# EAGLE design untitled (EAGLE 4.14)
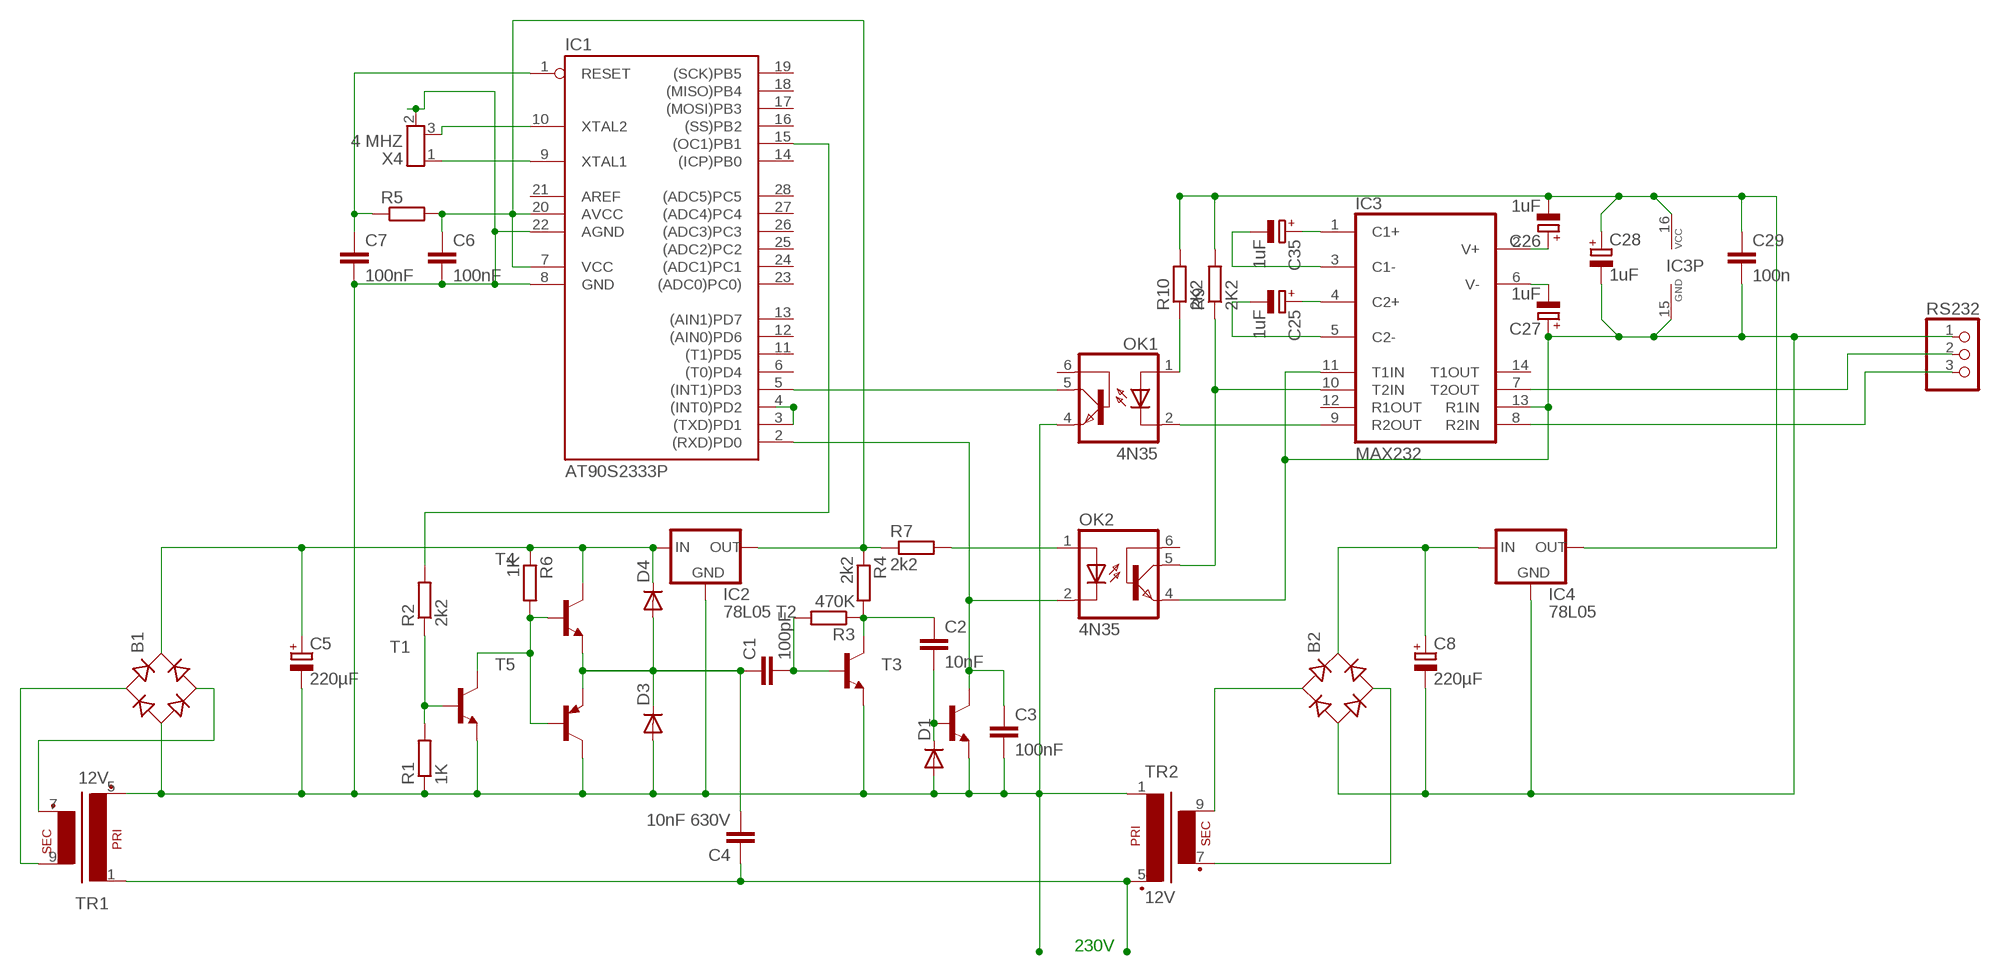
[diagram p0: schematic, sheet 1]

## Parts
B1  B-DIL  [B-DIL]
B2  B-DIL  [B-DIL]
C1  100pF  C-EU050-024X044  [C050-024X044]
C2  10nF  C-EU025-024X044  [C025-024X044]
C3  100nF  C-EU050-024X044  [C050-024X044]
C4  10nF 630V  C-EU102-043X133  [C102-043X133]
C5  220µF  CPOL-EUE5-10.5  [E5-10,5]
C6  100nF  C-EU050-024X044  [C050-024X044]
C7  100nF  C-EU050-024X044  [C050-024X044]
C8  220µF  CPOL-EUE5-10.5  [E5-10,5]
C25  1uF  CPOL-EUE2.5-5  [E2,5-5]
C26  1uF  CPOL-EUE2.5-5  [E2,5-5]
C27  1uF  CPOL-EUE2.5-5  [E2,5-5]
C28  1uF  CPOL-EUE2.5-5  [E2,5-5]
C29  100n  C-EUC1206  [C1206]
C35  1uF  CPOL-EUE2.5-5  [E2,5-5]
D1  DIODE-D-2.5  [D-2.5]
D3  DIODE-D-5  [D-5]
D4  DIODE-D-2.5  [D-2.5]
IC1  AT90S2333P  [DIL28-3]
IC2  78L05  78XXS  [78XXS]
IC3  MAX232  [DIL16]
IC4  78L05  78XXS  [78XXS]
OK1  4N35  [DIL06]
OK2  4N35  [DIL06]
R1  1K  R-EU_0207/5V  [0207/5V]
R2  2k2  R-EU_0207/5V  [0207/5V]
R3  470K  R-EU_0207/2V  [0207/2V]
R4  2k2  R-EU_0207/2V  [0207/2V]
R5  R-EU_0207/2V  [0207/2V]
R6  1K  R-EU_0207/2V  [0207/2V]
R7  2k2  R-EU_0207/2V  [0207/2V]
R9  2K2  R-EU_0207/2V  [0207/2V]
R10  2K2  R-EU_0207/2V  [0207/2V]
RS232  PINHD-1X3  [1X03]
T1  BC547A-NPN-TO92-EBC  [TO92-EBC]
T2  BC547A-NPN-TO92-EBC  [TO92-EBC]
T3  BC547A-NPN-TO92-EBC  [TO92-EBC]
T4  BC547A-NPN-TO92-EBC  [TO92-EBC]
T5  BC558A-PNP-TO92-EBC  [TO92-EBC]
TR1  12V  EI30-1  [EI30-1]
TR2  12V  EI30-1  [EI30-1]
X4  4 MHZ  RESONZTT  [RESONZTT]

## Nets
GND1: B1.- C3.2 C5.- C6.2 C7.2 D1.A D3.A IC1.8(GND) IC1.22(AGND) IC2.GND OK1.4(EMI) R1.1 T1.E T2.E T3.E T5.C TR1.5 TR2.1 X4.2(GND)
GND2: B2.- C8.- C27.+ C28.- C29.2 IC3.11(T1IN) IC3.13(R1IN) IC3.15(GND) IC4.GND OK2.4(EMI) RS232.1
N$1: R1.2 R2.1 T1.B
N$2: OK1.1(A) R10.1
N$3: C2.1 R3.1 R4.2 T2.C
N$4: C2.2 D1.C T3.B
N$5: IC1.15((OC1)PB1) R2.2
N$6: C1.2 R3.2 T2.B
N$7: IC1.3((TXD)PD1) IC1.4((INT0)PD2)
N$8: C4.1 TR1.1 TR2.5
N$9: OK2.1(A) R7.2
N$10: IC3.10(T2IN) OK2.5(COL) R9.1
N$11: C7.1 IC1.1(RESET) R5.1
N$12: C6.1 IC1.7(VCC) IC1.20(AVCC) IC2.OUT R4.1 R5.2 R7.1
N$13: C1.1 C4.2 D3.C D4.A T4.E T5.E
N$14: B1.+ C5.+ D4.C IC2.IN R6.1 T4.C
N$15: R6.2 T1.C T4.B T5.B
N$16: IC1.5((INT1)PD3) OK1.5(COL)
N$17: C3.1 IC1.2((RXD)PD0) OK2.2(C) T3.C
N$18: B2.AC1 TR2.9
N$19: B1.AC2 TR1.7
N$20: B1.AC1 TR1.9
N$21: B2.AC2 TR2.7
N$23: B2.+ C8.+ IC4.IN
N$52: IC1.9(XTAL1) X4.1(X1)
N$53: IC1.10(XTAL2) X4.3(X2)
N$64: C25.+ IC3.4(C2+)
N$66: C35.+ IC3.1(C1+)
N$67: C25.- IC3.5(C2-)
N$68: C35.- IC3.3(C1-)
N$69: C27.- IC3.6(V-)
N$70: C26.+ IC3.2(V+)
N$73: IC3.8(R2IN) RS232.3
N$74: IC3.9(R2OUT) OK1.2(C)
N$77: IC3.7(T2OUT) RS232.2
VCCBATT: C26.- C28.+ C29.1 IC3.16(VCC) IC4.OUT R9.2 R10.2
Unconnected: IC1.6((T0)PD4) IC1.11((T1)PD5) IC1.12((AIN0)PD6) IC1.13((AIN1)PD7) IC1.14((ICP)PB0) IC1.16((SS)PB2) IC1.17((MOSI)PB3) IC1.18((MISO)PB4) IC1.19((SCK)PB5) IC1.23((ADC0)PC0)) IC1.24((ADC1)PC1) IC1.25((ADC2)PC2) IC1.26((ADC3)PC3) IC1.27((ADC4)PC4) IC1.28((ADC5)PC5) IC3.12(R1OUT) IC3.14(T1OUT) OK1.6(BAS) OK2.6(BAS)

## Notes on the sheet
- 230V

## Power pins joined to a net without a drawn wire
AREF: IC1.21(AREF)

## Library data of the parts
B1 B2 = rectifier:B-DIL: RECTIFIER
C1-C4 C6 C7 C29 = rcl:C-EU: CAPACITOR, European symbol
C5 C8 C25-C28 C35 = rcl:CPOL-EU: POLARIZED CAPACITOR, European symbol
D1 D3 D4 = diode:DIODE-: DIODE
IC1 = atmel:AT90S2333P: MICROCONTROLLER 2 Kbytes FLASH 128 bytes SRAM 128 bytes EEPROM UART 6-channel 10-bit ADC
IC2 IC4 = v-reg:78XXS: VOLTAGE REGULATOR
IC3 = maxim:MAX232: RS232 TRANSEIVER
OK1 OK2 = optocoupler:4N35: MOTOROLA OPTO COUPLER
R1-R7 R9 R10 = rcl:R-EU_: RESISTOR, European symbol
RS232 = pinhead:PINHD-1X3: PIN HEADER
T1-T4 = transistor:*-NPN-: NPN Transistror
T5 = transistor:*-PNP-: PNP Transistror
TR1 TR2 = trafo:EI30-1: TRANSFORMER 1 primary winding, 1 secondary winding ERA
X4 = ADS:RESONZTT

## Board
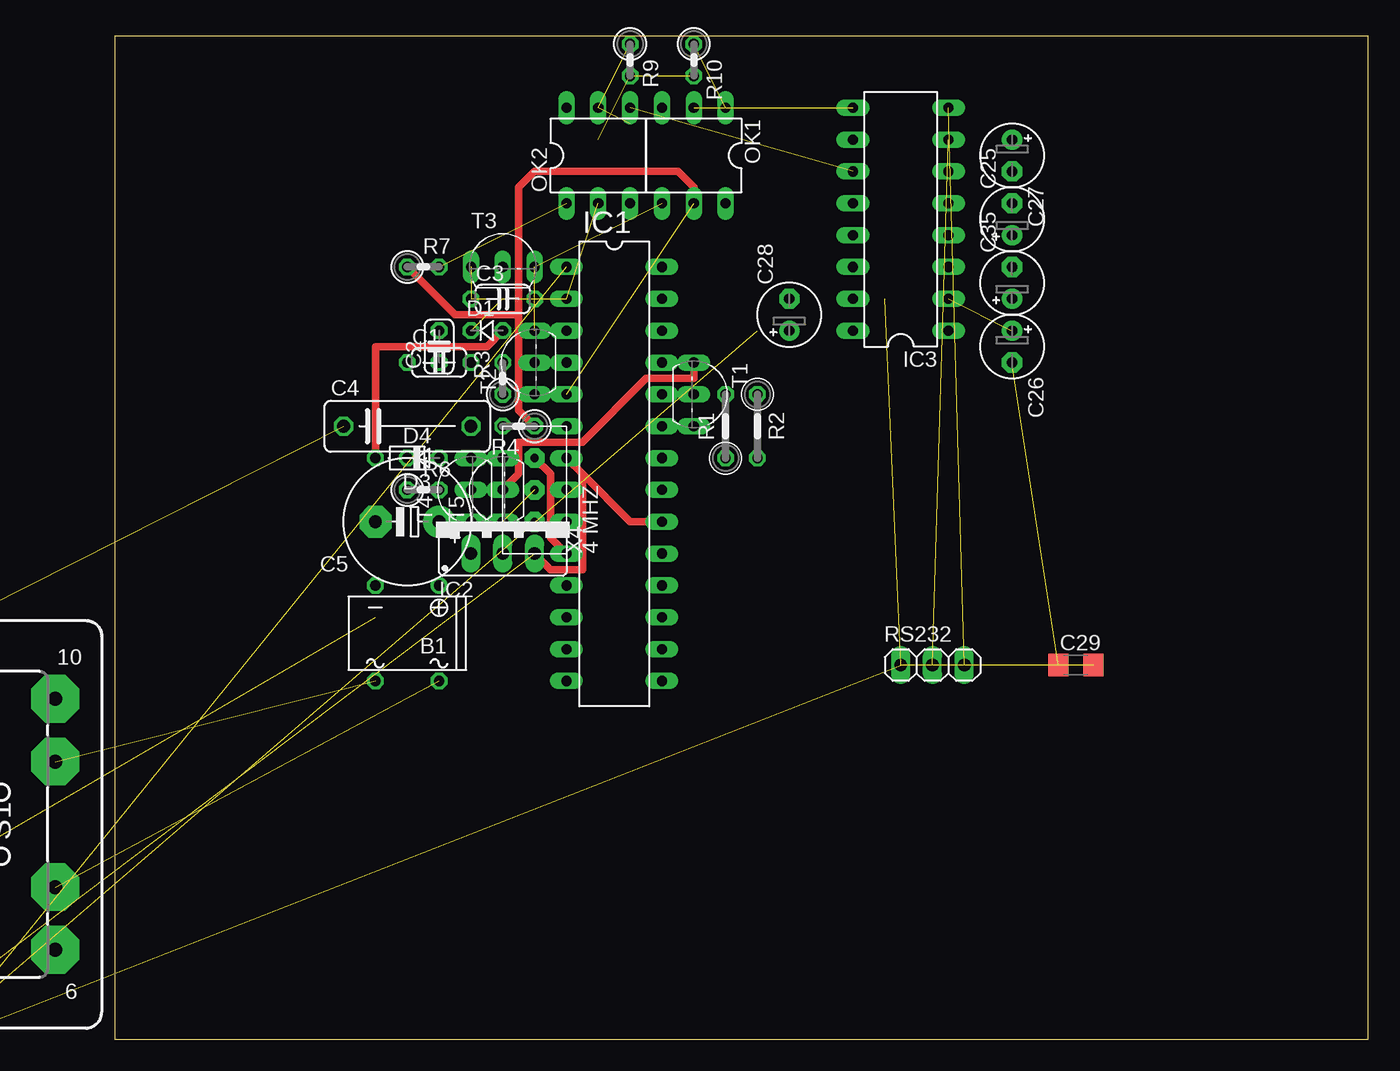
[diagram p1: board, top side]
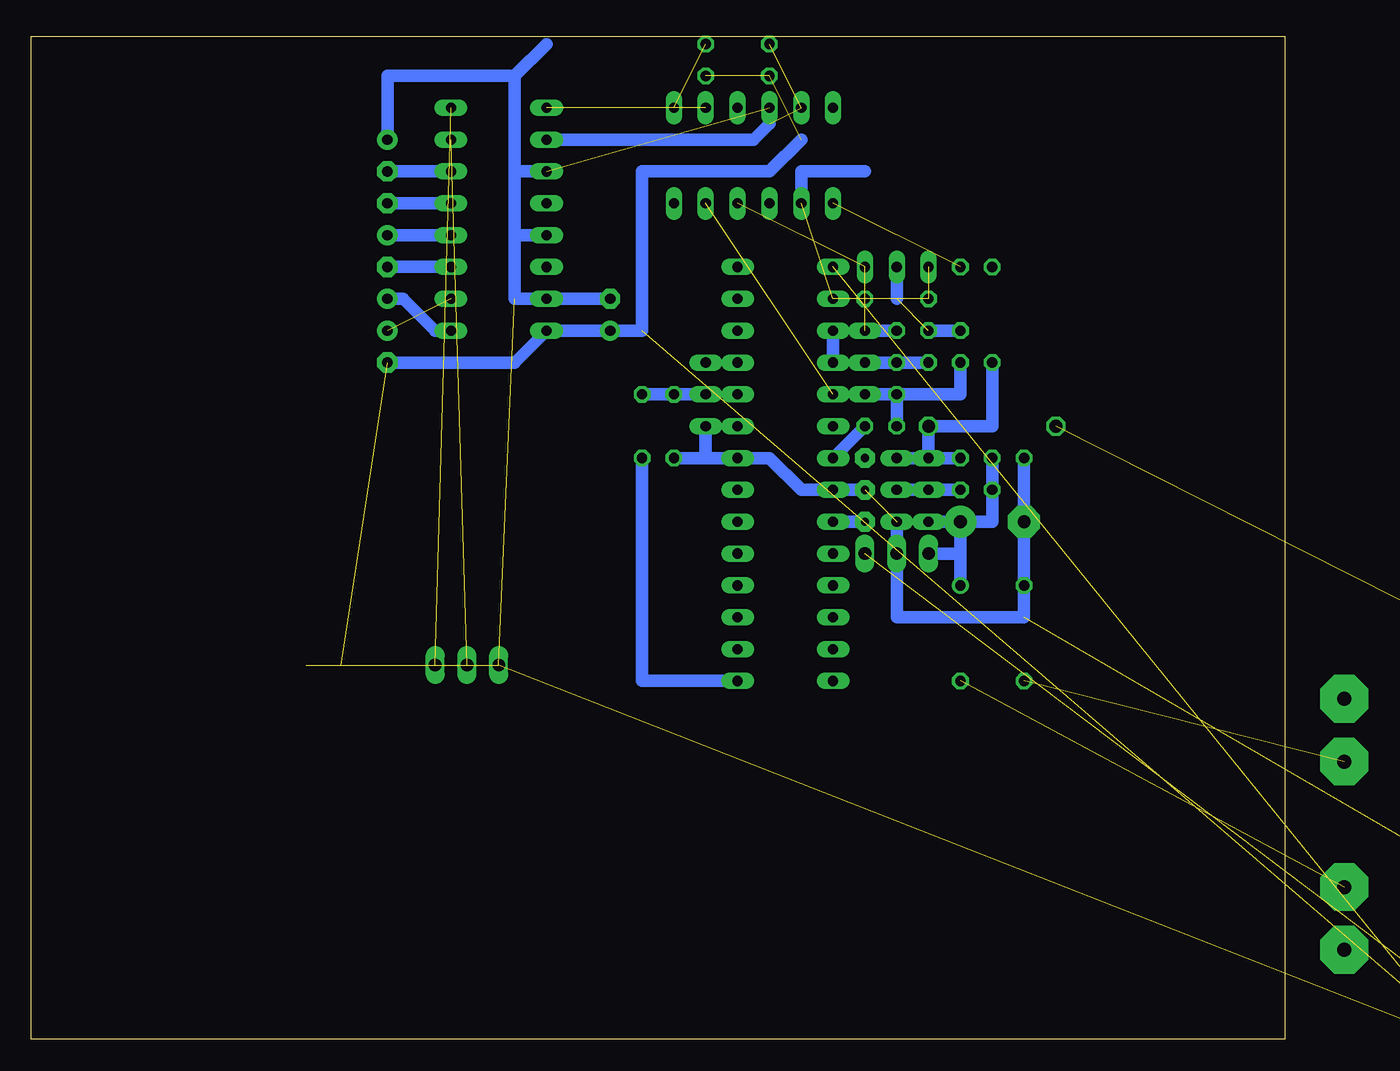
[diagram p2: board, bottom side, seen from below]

Size 100 x 80 mm. Coordinates in mm from the lower left corner, seen from the top.
Outline: 0,0 100,0 100,80 0,80 0,0
Copper layers (1*16): Top 0.035mm / dielectric 1.5mm / Bottom 0.035mm
Design rules "default": minimum track width 10mil, minimum drill 24mil, track to track 8mil, track to pad 8mil, pad to pad 8mil, via to via 8mil, smd to smd 8mil, copper to edge 40mil, drill to drill 8mil, minimum pad ring 10mil, minimum via ring 8mil, stop-mask expansion 4mil, vias tented up to drill 0mil, thermal gap 10mil

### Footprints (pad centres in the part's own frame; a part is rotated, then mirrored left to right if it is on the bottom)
B-DIL = drill 0.813 round: + -2.54,-3.81 | drill 0.813 octagon: - 2.54,-3.81; AC1 2.54,3.81; AC2 -2.54,3.81
C050-024X044 = drill 0.813 octagon: 1 -2.54,0; 2 2.54,0
C025-024X044 = drill 0.813 octagon: 1 -1.27,0; 2 1.27,0
C102-043X133 = drill 1.016 octagon: 1 -5.08,0; 2 5.08,0
E5-10,5 = drill 1.016 pad 2.54 round: + -2.54,0 | drill 1.016 pad 2.54 octagon: - 2.54,0
E2,5-5 = drill 0.813 pad 1.6 round: + -1.27,0 | drill 0.813 pad 1.6 octagon: - 1.27,0
C1206 = smd 1.6 x 1.8: 1 -1.4,0; 2 1.4,0
D-2.5 = drill 0.813 octagon: A 1.27,0; C -1.27,0
D-5 = drill 0.813 octagon: A 2.54,0; C -2.54,0
DIL28-3 = drill 0.813 long: 1 -16.51,-3.81; 2 -13.97,-3.81; 3 -11.43,-3.81; 4 -8.89,-3.81; 5 -6.35,-3.81; 6 -3.81,-3.81; 7 -1.27,-3.81; 8 1.27,-3.81; 9 3.81,-3.81; 10 6.35,-3.81; 11 8.89,-3.81; 12 11.43,-3.81; 13 13.97,-3.81; 14 16.51,-3.81; 15 16.51,3.81; 16 13.97,3.81; 17 11.43,3.81; 18 8.89,3.81; 19 6.35,3.81; 20 3.81,3.81; 21 1.27,3.81; 22 -1.27,3.81; 23 -3.81,3.81; 24 -6.35,3.81; 25 -8.89,3.81; 26 -11.43,3.81; 27 -13.97,3.81; 28 -16.51,3.81
78XXS = drill 1.016 long: GND 0,-2.54; IN -2.54,-2.54; OUT 2.54,-2.54
DIL16 = drill 0.813 long: 1 -8.89,-3.81; 2 -6.35,-3.81; 3 -3.81,-3.81; 4 -1.27,-3.81; 5 1.27,-3.81; 6 3.81,-3.81; 7 6.35,-3.81; 8 8.89,-3.81; 9 8.89,3.81; 10 6.35,3.81; 11 3.81,3.81; 12 1.27,3.81; 13 -1.27,3.81; 14 -3.81,3.81; 15 -6.35,3.81; 16 -8.89,3.81
DIL06 = drill 0.813 long: 1 -2.54,-3.81; 2 0,-3.81; 3 2.54,-3.81; 4 2.54,3.81; 5 0,3.81; 6 -2.54,3.81
0207/5V = drill 0.813 octagon: 1 -2.54,0; 2 2.54,0
0207/2V = drill 0.813 octagon: 1 -1.27,0; 2 1.27,0
1X03 = drill 1.016 long: 1 -2.54,0; 2 0,0; 3 2.54,0
TO92-EBC = drill 0.813 long: B 0,-1.27; C -2.54,-1.27; E 2.54,-1.27
EI30-1 = drill 1.118 pad 3.81 octagon: 1 -10.008,10.008; 5 -10.008,-10.008; 6 10.008,-10.008; 7 10.008,-5.004; 9 10.008,5.004; 10 10.008,10.008
RESONZTT = drill 0.66 pad 1.575 octagon: 1 0,0; 2 2.54,0; 3 5.08,0

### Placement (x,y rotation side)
B1  23.33,32.38 180 top
B2  not placed on the board
C1  25.87,53.97 0 top
C2  25.87,55.24 90 top
C3  30.95,59.05 0 top
C4  23.33,48.89 0 top
C5  [E5-10,5]  23.33,41.27 180 top
C6  not placed on the board
C7  not placed on the board
C8  [E5-10,5]  not placed on the board
C25  71.59,65.4 90 top
C26  71.59,55.24 270 top
C27  71.59,70.48 270 top
C28  53.81,57.78 90 top
C29  76.67,29.84 0 top
C35  71.59,60.32 90 top
D1  29.68,56.51 0 top
D3  23.33,46.35 180 top
D4  24.6,46.35 0 top
IC1  39.84,45.08 270 top
IC2  30.95,41.27 0 top
IC3  62.7,65.4 90 top
IC4  not placed on the board
OK1  46.19,70.48 180 top
OK2  38.57,70.48 0 top
R1  48.73,48.89 90 top
R2  51.27,48.89 270 top
R3  [0207/2V]  30.95,52.7 90 top
R4  32.22,48.89 180 top
R5  not placed on the board
R6  24.6,43.81 0 top
R7  24.6,61.59 0 top
R9  [0207/2V]  41.11,78.1 270 top
R10  [0207/2V]  46.19,78.1 270 top
RS232  65.24,29.84 0 top
T1  47.46,51.43 270 top
T2  32.22,53.97 90 top
T3  30.95,62.86 0 top
T4  27.14,43.81 90 top
T5  29.68,43.81 90 top
TR1  [EI30-1]  not placed on the board
TR2  [EI30-1]  not placed on the board
X4  33.49,41.27 90 top

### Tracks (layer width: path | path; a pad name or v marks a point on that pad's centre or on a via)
GND1  (8 unrouted)
  Top 0.61: D1.A 29.68,55.24 20.79,55.24 D3.A
  Bottom 1.016: X4.2 IC1.8 38.57,43.81 41.11,46.35 IC1.22 | T1.E 46.19,46.35 IC1.22 | IC1.22 R1.1 | D1.A T2.E | IC2.GND T5.C 30.95,33.65 20.79,33.65 B1.- C5.- D3.A
GND2  (6 unrouted)
  Bottom 1.016: C28.- IC3.15 61.43,59.05 61.43,64.13 | 61.43,76.83 58.89,79.37 | 61.43,69.21 61.43,76.83 | C27.+ 71.59,76.83 61.43,76.83 | 61.43,69.21 IC3.11 | 61.43,64.13 61.43,69.21 | 61.43,64.13 IC3.13
N$1
  Bottom 1.016: T1.B R1.2 R2.1
N$2  (1 unrouted)
N$3
  Bottom 1.016: R3.1 T2.C | R3.1 25.87,51.43 C2.1 | R3.1 R4.2
N$4  (1 unrouted)
  Bottom 1.016: C2.2 D1.C | 30.95,59.05 T3.B
N$5
  Bottom 1.016: R2.2 51.27,28.57 IC1.15
N$6
  Bottom 1.016: T2.B R3.2 C1.2
N$7
  Bottom 1.016: IC1.4 IC1.3
N$8  (2 unrouted)
N$9  (1 unrouted)
N$10  (2 unrouted)
  Bottom 1.016: 41.11,73.02 42.38,71.75 IC3.10
N$11  (2 unrouted)
N$12  (2 unrouted)
  Top 0.61: R4.1 32.22,50.16 32.22,57.78 | 32.22,57.78 27.14,57.78 R7.1 | IC2.OUT 34.76,37.46 37.3,37.46 37.3,45.08 | 37.3,45.08 IC1.7 | IC1.20 41.11,41.27 37.3,45.08 | 46.19,67.94 44.92,69.21 33.49,69.21 32.22,67.94 32.22,57.78
  Bottom 1.016: IC1.7 R4.1
N$13
  Bottom 1.016: C1.1 23.33,48.89 C4.2 T4.E | T4.E T5.E | D3.C T4.E
N$14
  Bottom 1.016: R6.1 23.33,41.27 C5.+ | R6.1 D4.C R6.1 | C5.+ T4.C | B1.+ 25.87,38.73 | 25.87,38.73 C5.+ | 25.87,38.73 IC2.IN
N$15
  Top 0.61: T1.C 46.19,52.7 42.38,52.7 37.3,47.62 32.22,47.62 32.22,45.08 T5.B
  Bottom 1.016: T5.B T4.B R6.2
N$16  (1 unrouted)
N$17  (3 unrouted)
  Bottom 1.016: 33.49,69.21 38.57,69.21 OK2.2
N$18  (1 unrouted)
N$19  (1 unrouted)
N$20  (1 unrouted)
N$21  (1 unrouted)
N$23  (2 unrouted)
N$52
  Bottom 1.016: X4.1 IC1.9
N$53
  Top 0.61: X4.3 34.76,45.08 34.76,40 IC1.10
N$64
  Bottom 1.016: C25.+ IC3.4
N$66
  Bottom 1.016: C35.+ 70.32,59.05 67.78,56.51 IC3.1
N$67
  Bottom 1.016: C25.- IC3.5
N$68
  Bottom 1.016: C35.- IC3.3
N$69
  Bottom 1.016: C27.- IC3.6
N$70  (1 unrouted)
N$73  (1 unrouted)
N$74  (1 unrouted)
N$77  (1 unrouted)
VCCBATT  (4 unrouted)
  Bottom 1.016: C26.- 61.43,53.97 IC3.16 C28.+ 51.27,56.51 51.27,69.21 41.11,69.21 38.57,71.75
